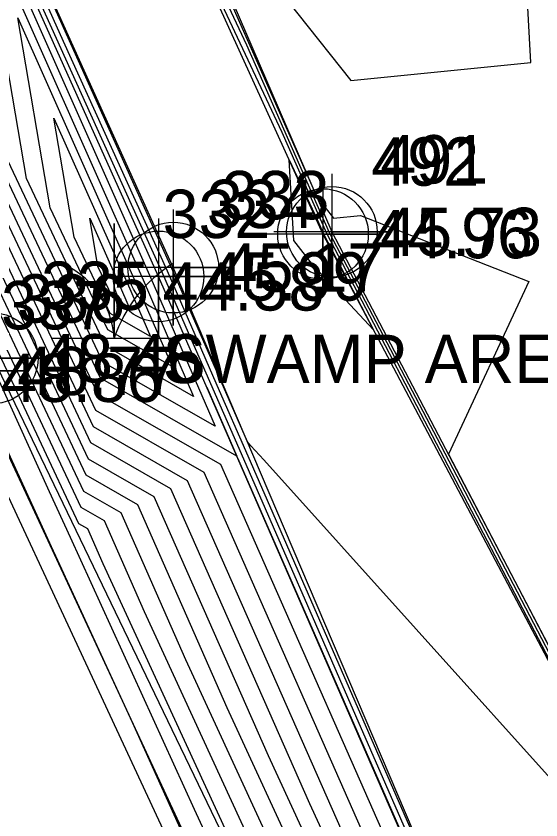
# Model space of a CAD drawing. Extents: x 2090860 to 2091277, y 159470 to 160080.
# Drawn here: x 2090981.55 to 2091008.71, y 159942.65 to 159984.21 of the extents above; entities that cross this region are included whole.
import ezdxf

# ---------------------------------------------------------------- set-up
doc = ezdxf.new("R2010")
doc.units = 0
for name, color, linetype in [('DTM Contours Major', 7, 'Continuous'), ('DTM Contours Minor', 7, 'Continuous'), ('Exist DTM Breakline', 7, 'Continuous'), ('Exist DTM Breakline Cogo Elevation', 7, 'Continuous'), ('Exist DTM Breakline Cogo Number', 7, 'Continuous'), ('Exist DTM Breakline Cogo Point CELL', 7, 'Continuous'), ('Exist Hydro Swamp or Marsh', 7, 'Continuous'), ('Exist Hydro Swamp or Marsh Cogo Comment', 7, 'Continuous'), ('Exist Hydro Swamp or Marsh Cogo Elevation', 7, 'Continuous'), ('Exist Hydro Swamp or Marsh Cogo Number', 7, 'Continuous'), ('Exist Roads EOP', 7, 'Continuous'), ('Exist Roads EOP Cogo Elevation', 7, 'Continuous'), ('Exist Roads EOP Cogo Number', 7, 'Continuous'), ('Exist Roads EOP Cogo Point CELL', 7, 'Continuous'), ('Exist Roads EOT', 7, 'Continuous'), ('Exist Roads EOT Cogo Elevation', 7, 'Continuous'), ('Exist Roads EOT Cogo Number', 7, 'Continuous')]:
    doc.layers.add(name, color=color, linetype=linetype)

msp = doc.modelspace()

# ---------------------------------------------------------------- linework, layer by layer
at = {"layer": 'DTM Contours Major'}
for points in [[(2090956.341, 160065.361), (2090956.351, 160065.306), (2090959.29, 160058.77), (2090968.77, 160038.007), (2090971.862, 160031.101), (2090977.516, 160018.706), (2090978.126, 160018.174), (2090989.29, 159992.953), (2090989.994, 159992.181), (2090990.384, 159991.663), (2090990.651, 159991.238), (2090998.867, 159980.879), (2091008.192, 159981.808), (2091007.743, 159990), (2091008.559, 159991.441), (2091010, 159993.309)], [(2091021.025, 159898.877), (2091011.639, 159919.455), (2091005.482, 159932.957), (2091005.012, 159933.952), (2090993.094, 159961.193), (2090992.991, 159961.428), (2090991.418, 159965.023), (2090992.968, 159961.452), (2090985.925, 159965.485), (2090984.33, 159968.87), (2090979.616, 159978.837), (2090976.348, 159997.974), (2090975.965, 159998.781), (2090963.783, 160025.207), (2090963.068, 160026.714), (2090951.202, 160052.433), (2090950.873, 160053.127), (2090947.083, 160061.339), (2090947.113, 160061.357)], [(2091021.18, 159890.907), (2091013.639, 159907.174), (2091008.516, 159918.108), (2091005.725, 159924.066), (2091001.855, 159932.408), (2090996.755, 159943.477), (2090989.564, 159959.773), (2090985.428, 159962.142), (2090982.708, 159967.911), (2090974.675, 159984.898), (2090972.744, 159996.202), (2090967.23, 160007.833), (2090960.061, 160023.383), (2090954.323, 160035.484), (2090947.368, 160050.56), (2090945.472, 160054.558), (2090943.253, 160059.365), (2090943.413, 160059.46)], [(2091015.949, 159893.794), (2091005.233, 159916.667), (2090999.394, 159929.129), (2090998.605, 159930.829), (2090988.204, 159953.404), (2090986.126, 159958.114), (2090984.93, 159958.799), (2090981.087, 159966.952), (2090969.734, 159990.958), (2090969.141, 159994.43), (2090958.495, 160016.884), (2090956.34, 160021.56), (2090945.578, 160044.255), (2090943.533, 160048.687), (2090940.07, 160055.988), (2090939.423, 160057.391), (2090939.712, 160057.563)], [(2090983.506, 159978.934), (2090987.313, 159970.385), (2090988.506, 159967.635), (2090986.423, 159968.828), (2090985.951, 159969.829), (2090984.557, 159972.777), (2090983.506, 159978.934)], [(2090995.683, 159976.767), (2090997.126, 159973.693), (2090997.457, 159972.941), (2091000.053, 159967.978), (2090996.895, 159971.359), (2090995.919, 159972.596), (2090995.683, 159976.767)]]:
    msp.add_lwpolyline(points, dxfattribs=at)
at = {"layer": 'DTM Contours Minor'}
for points in [[(2090955.723, 160065.24), (2090955.755, 160065.066), (2090965.14, 160044.195), (2090968.09, 160037.734), (2090976.266, 160019.474), (2090976.714, 160018.492), (2090978.176, 160017.217), (2090985.815, 159999.959), (2090989.474, 159991.243), (2090993.478, 159982.712), (2090997.759, 159973.016), (2091003.522, 159962), (2091011.65, 159946.449)], [(2090956.032, 160065.301), (2090956.053, 160065.186), (2090962.215, 160051.483), (2090968.43, 160037.87), (2090974.064, 160025.288), (2090977.115, 160018.599), (2090978.151, 160017.695), (2090988.003, 159995.439), (2090989.746, 159991.286), (2090991.654, 159987.221), (2090997.113, 159974.859), (2090997.983, 159973.762), (2090999.376, 159973.9), (2091008.084, 159970.483), (2091003.919, 159961.557), (2091011.802, 159946.475)], [(2091025.102, 159892.473), (2091012.728, 159918.738), (2091012.329, 159919.613), (2091012.067, 159920.187), (2091005.42, 159934.274), (2091005.163, 159934.86), (2090993.441, 159961.728), (2090992.08, 159964.838), (2090989.382, 159971.02), (2090984.007, 159982.894), (2090977.042, 159998.364), (2090971.588, 160010.408), (2090964.702, 160025.709), (2090959.133, 160037.996), (2090952.362, 160053.053), (2090950.665, 160056.795), (2090948.359, 160061.924), (2090950.641, 160063.035)], [(2091024.64, 159892.328), (2091016.876, 159908.808), (2091011.984, 159919.534), (2091008.774, 159926.572), (2091005.216, 159934.113), (2090999.129, 159948.027), (2090993.216, 159961.578), (2090990.478, 159967.834), (2090989.149, 159970.881), (2090979.664, 159991.834), (2090976.792, 159998.213), (2090966.504, 160020.929), (2090964.429, 160025.539), (2090952.994, 160050.772), (2090952.056, 160052.858), (2090948.153, 160061.461), (2090947.998, 160061.806), (2090948.151, 160061.88)], [(2091023.606, 159891.972), (2091011.906, 159917.209), (2091010.978, 159919.19), (2091010.473, 159920.269), (2091004.292, 159933.592), (2091003.168, 159936.032), (2090992.143, 159961.018), (2090985.801, 159964.649), (2090983.924, 159968.63), (2090978.381, 159980.353), (2090975.447, 159997.531), (2090973.781, 160001.044), (2090962.852, 160024.751), (2090960.882, 160028.906), (2090950.243, 160051.965), (2090949.523, 160053.484), (2090946.126, 160060.846), (2090946.188, 160060.883)], [(2091022.798, 159891.617), (2091012.484, 159913.864), (2091010.158, 159918.829), (2091008.89, 159921.535), (2091003.48, 159933.198), (2091001.03, 159938.513), (2090991.283, 159960.603), (2090985.677, 159963.813), (2090983.519, 159968.391), (2090977.145, 159981.868), (2090974.546, 159997.088), (2090971.598, 160003.307), (2090961.922, 160024.295), (2090958.696, 160031.099), (2090949.285, 160051.497), (2090948.173, 160053.842), (2090945.168, 160060.352), (2090945.263, 160060.408)], [(2091021.989, 159891.262), (2091013.061, 159910.519), (2091009.337, 159918.469), (2091007.307, 159922.8), (2091002.667, 159932.803), (2090998.893, 159940.995), (2090990.424, 159960.188), (2090985.552, 159962.978), (2090983.114, 159968.151), (2090975.91, 159983.383), (2090973.645, 159996.645), (2090969.414, 160005.57), (2090960.992, 160023.839), (2090956.509, 160033.292), (2090948.326, 160051.028), (2090946.822, 160054.2), (2090944.211, 160059.859), (2090944.338, 160059.934)], [(2091014.217, 159903.829), (2091007.695, 159917.748), (2091004.142, 159925.332), (2091001.042, 159932.013), (2090994.617, 159945.959), (2090988.704, 159959.359), (2090985.303, 159961.306), (2090982.303, 159967.671), (2090973.44, 159986.413), (2090971.844, 159995.759), (2090965.046, 160010.096), (2090959.131, 160022.927), (2090952.137, 160037.677), (2090946.409, 160050.092), (2090944.121, 160054.915), (2090942.296, 160058.872), (2090942.487, 160058.986)], [(2091014.794, 159900.484), (2091006.874, 159917.387), (2091002.559, 159926.597), (2091000.23, 159931.619), (2090992.479, 159948.441), (2090987.845, 159958.944), (2090985.179, 159960.47), (2090981.898, 159967.432), (2090972.204, 159987.928), (2090970.943, 159995.316), (2090962.863, 160012.359), (2090958.2, 160022.472), (2090949.95, 160039.87), (2090945.45, 160049.623), (2090942.771, 160055.273), (2090941.338, 160058.378), (2090941.562, 160058.512)], [(2091015.372, 159897.139), (2091006.054, 159917.027), (2091000.976, 159927.863), (2090999.417, 159931.224), (2090990.342, 159950.923), (2090986.985, 159958.529), (2090985.054, 159959.635), (2090981.492, 159967.192), (2090970.969, 159989.443), (2090970.042, 159994.873), (2090960.679, 160014.622), (2090957.27, 160022.016), (2090947.764, 160042.063), (2090944.492, 160049.155), (2090941.421, 160055.631), (2090940.381, 160057.885), (2090940.637, 160058.037)], [(2091016.527, 159890.449), (2091004.412, 159916.306), (2090997.811, 159930.395), (2090997.792, 159930.434), (2090986.066, 159955.886), (2090985.266, 159957.699), (2090984.806, 159957.963), (2090980.682, 159966.713), (2090968.499, 159992.473), (2090968.24, 159993.988), (2090956.311, 160019.147), (2090955.409, 160021.104), (2090943.391, 160046.448), (2090942.575, 160048.218), (2090938.72, 160056.346), (2090938.465, 160056.898), (2090938.787, 160057.089)], [(2091009.719, 159902.684), (2091003.488, 159915.918), (2091000.285, 159922.734), (2090996.873, 159929.981), (2090990.78, 159943.197), (2090984.364, 159957.258), (2090983.277, 159959.617), (2090980.176, 159966.423), (2090978.448, 159970.155), (2090967.363, 159993.547), (2090966.269, 159995.909), (2090955.847, 160017.91), (2090953.21, 160023.496), (2090943.221, 160044.585), (2090940.726, 160049.87), (2090937.604, 160056.462), (2090937.861, 160056.615)], [(2091015.092, 159888.281), (2091005.494, 159908.792), (2091002.253, 159915.399), (2090998.196, 159923.671), (2090995.587, 159929.309), (2090993.655, 159934.254), (2090987.577, 159947.689), (2090983.614, 159956.284), (2090983.391, 159956.773), (2090979.397, 159965.44), (2090979.189, 159965.897), (2090967.415, 159991.324), (2090966.567, 159993.113), (2090960.639, 160005.911), (2090959.796, 160007.69), (2090947.752, 160033.198), (2090947.057, 160034.665), (2090937.109, 160055.735), (2090936.921, 160056.131), (2090936.936, 160056.14)], [(2091012.106, 159925.968), (2091007.685, 159935.502), (2091010.132, 159943.75), (2090994.374, 159961.259), (2090993.699, 159961.981), (2090993.523, 159962.203), (2090989.615, 159971.158), (2090988.349, 159973.954), (2090977.292, 159998.516), (2090976.671, 159999.886), (2090968.466, 160018.121), (2090977.233, 160001.212), (2090985.269, 159999.581), (2090977.053, 160017.74)], [(2090977.053, 160017.74), (2090978.201, 160016.738), (2090983.627, 160004.48), (2090989.202, 159991.2), (2090995.302, 159978.202), (2090997.608, 159972.979), (2091009.774, 159949.721)], [(2090977.922, 159994.472), (2090988.528, 159970.658), (2090991.852, 159962.998), (2090986.05, 159966.321), (2090984.735, 159969.11), (2090980.851, 159977.322), (2090977.922, 159994.472)], [(2090979.783, 159989.293), (2090988.123, 159970.567), (2090990.737, 159964.544), (2090986.174, 159967.156), (2090985.14, 159969.35), (2090982.086, 159975.807), (2090979.783, 159989.293)], [(2090981.644, 159984.113), (2090987.718, 159970.476), (2090989.621, 159966.09), (2090986.299, 159967.992), (2090985.546, 159969.589), (2090983.322, 159974.292), (2090981.644, 159984.113)], [(2090985.367, 159973.754), (2090986.908, 159970.294), (2090987.391, 159969.181), (2090986.547, 159969.664), (2090986.356, 159970.069), (2090985.792, 159971.262), (2090985.367, 159973.754)]]:
    msp.add_lwpolyline(points, dxfattribs=at)
at = {"layer": 'Exist DTM Breakline'}
for points in [[(2090956.622, 160065.416), (2090978.09, 160018.859), (2090997.895, 159973.05), (2091025.359, 159920.65)], [(2090955.177, 160064.832), (2090976.645, 160018.474), (2090997.432, 159972.935), (2091025.272, 159920.294)], [(2091061.634, 159820.633), (2091041.562, 159858.316), (2091025.181, 159892.498), (2091005.429, 159934.281), (2090989.687, 159971.201), (2090948.616, 160062.008)], [(2091060.143, 159819.743), (2091040.416, 159857.574), (2091023.862, 159892.084), (2091004.981, 159933.927), (2090988.922, 159970.746), (2090947.972, 160061.797)], [(2091054.851, 159814.302), (2091016.781, 159888.977), (2090997.773, 159930.425), (2090980.346, 159966.514), (2090937.845, 160056.578)]]:
    msp.add_lwpolyline(points, dxfattribs=at)
at = {"layer": 'Exist DTM Breakline Cogo Point CELL'}
for points in [[(2090997.432, 159975.935), (2090997.432, 159969.935), (2090997.432, 159972.935), (2091000.432, 159972.935), (2090994.432, 159972.935)], [(2090997.895, 159976.05), (2090997.895, 159970.05), (2090997.895, 159973.05), (2091000.895, 159973.05), (2090994.895, 159973.05)], [(2090989.687, 159974.201), (2090989.687, 159968.201), (2090989.687, 159971.201), (2090992.687, 159971.201), (2090986.687, 159971.201)], [(2090988.922, 159973.746), (2090988.922, 159967.746), (2090988.922, 159970.746), (2090991.922, 159970.746), (2090985.922, 159970.746)], [(2090980.346, 159969.514), (2090980.346, 159963.514), (2090980.346, 159966.514), (2090983.346, 159966.514), (2090977.346, 159966.514)]]:
    msp.add_lwpolyline(points, dxfattribs=at)
for centre in [(2090997.432, 159972.935), (2090997.895, 159973.05), (2090989.687, 159971.201), (2090988.922, 159970.746), (2090980.346, 159966.514)]:
    msp.add_circle(centre, 2.344, dxfattribs=at)
at = {"layer": 'Exist Hydro Swamp or Marsh'}
msp.add_line((2090986.632, 159970.232), (2090986.632, 159970.232), dxfattribs=at)
msp.add_lwpolyline([(2090983.407, 159967.558), (2090986.633, 159967.558), (2090986.633, 159973.475), (2090986.633, 159967.558), (2090989.858, 159967.558)], dxfattribs=at)
for centre, radius, start, end in [((2090982.033, 159967.225), 4.612, 4.1403, 67.535), ((2090993.474, 159965.285), 7.208, 122.1274, 161.6222)]:
    msp.add_arc(centre, radius, start, end, dxfattribs=at)
at = {"layer": 'Exist Roads EOP'}
msp.add_lwpolyline([(2091050.887, 159811.953), (2091031.567, 159853.358), (2091015.44, 159888.433), (2090996.018, 159929.558), (2090979.118, 159965.859), (2090960.144, 160006.791), (2090936.877, 160056.11)], dxfattribs=at)
at = {"layer": 'Exist Roads EOP Cogo Point CELL'}
msp.add_lwpolyline([(2090979.118, 159968.859), (2090979.118, 159962.859), (2090979.118, 159965.859), (2090982.118, 159965.859), (2090976.118, 159965.859)], dxfattribs=at)
at = {"layer": 'Exist Roads EOT'}
msp.add_lwpolyline([(2091050.358, 159811.619), (2091030.997, 159852.885), (2091014.318, 159887.944), (2090995.228, 159929.102), (2090978.274, 159965.509), (2090959.414, 160006.451), (2090936.296, 160055.791)], dxfattribs=at)

# ---------------------------------------------------------------- texts
at = {"layer": 'Exist DTM Breakline Cogo Elevation'}
for s, p in [('44.96', (2090999.932, 159971.685)), ('45.73', (2091000.395, 159971.8)), ('45.17', (2090992.187, 159969.951)), ('45.99', (2090991.422, 159969.496)), ('48.46', (2090982.846, 159965.264))]:
    msp.add_text(s, height=2.5, dxfattribs=at).set_placement(p)
at = {"layer": 'Exist DTM Breakline Cogo Number'}
for s, p in [('492', (2090999.932, 159975.435)), ('491', (2091000.395, 159975.55)), ('333', (2090992.187, 159973.701)), ('334', (2090991.422, 159973.246)), ('335', (2090982.846, 159969.014))]:
    msp.add_text(s, height=2.5, dxfattribs=at).set_placement(p)
at = {"layer": 'Exist Hydro Swamp or Marsh Cogo Comment'}
msp.add_text('SWAMP AREA', height=2.5, dxfattribs=at).set_placement((2090989.132, 159965.232))
at = {"layer": 'Exist Hydro Swamp or Marsh Cogo Elevation'}
msp.add_text('44.58', height=2.5, dxfattribs=at).set_placement((2090989.132, 159968.982))
at = {"layer": 'Exist Hydro Swamp or Marsh Cogo Number'}
msp.add_text('332', height=2.5, dxfattribs=at).set_placement((2090989.132, 159972.732))
at = {"layer": 'Exist Roads EOP Cogo Elevation'}
msp.add_text('48.77', height=2.5, dxfattribs=at).set_placement((2090981.618, 159964.609))
at = {"layer": 'Exist Roads EOP Cogo Number'}
msp.add_text('336', height=2.5, dxfattribs=at).set_placement((2090981.618, 159968.359))
at = {"layer": 'Exist Roads EOT Cogo Elevation'}
msp.add_text('48.86', height=2.5, dxfattribs=at).set_placement((2090980.774, 159964.259))
at = {"layer": 'Exist Roads EOT Cogo Number'}
msp.add_text('337', height=2.5, dxfattribs=at).set_placement((2090980.774, 159968.009))

doc.saveas('drawing.dxf')
